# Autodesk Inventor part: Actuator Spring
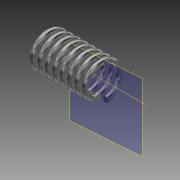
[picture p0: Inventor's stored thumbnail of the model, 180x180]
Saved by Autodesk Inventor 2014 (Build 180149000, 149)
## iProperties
Created: 2009-03
Part Number: Actuator Spring
Document SubType Name: Modeling
Designer: tangg
Density: 7.84 g/cm^3
Material: Steel, High Strength Low Alloy
Mass: 4.28111 g
Surface Area: 12.5295 cm^2
Volume: 0.54606 cm^3
Appearance: Steel - Polished
Author: tangg
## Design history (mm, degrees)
sketch "Sketch1"
  geometry: 1 further point
sketch "3D Sketch1"
  node "Helical Curve1" dims "d0" = 19.4056, "d1" = 80, "d2" = 10, "d3" = 0
workplane "Work Plane1"
sketch "Sketch2"
  geometry: C1 r 0.875 at (0, 0); 1 further point
  constraints: 1 centre point
  dimensions: "d5" = 1.75 diameter of C1
sweep "Sweep1" sketch "Sketch2" dims "d4" = 0
body "Solid1"
